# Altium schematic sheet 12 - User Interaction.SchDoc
size B; CompanyName: Microchip Technology Inc.; Organization: Microchip Technology; Address1: 2355 West Chandler Blvd.; Address2: Chandler, AZ  85224; Address4: USA; DocumentNumber: 12; SheetNumber: 12; SheetTotal: 13; SheetTitle: User Interaction
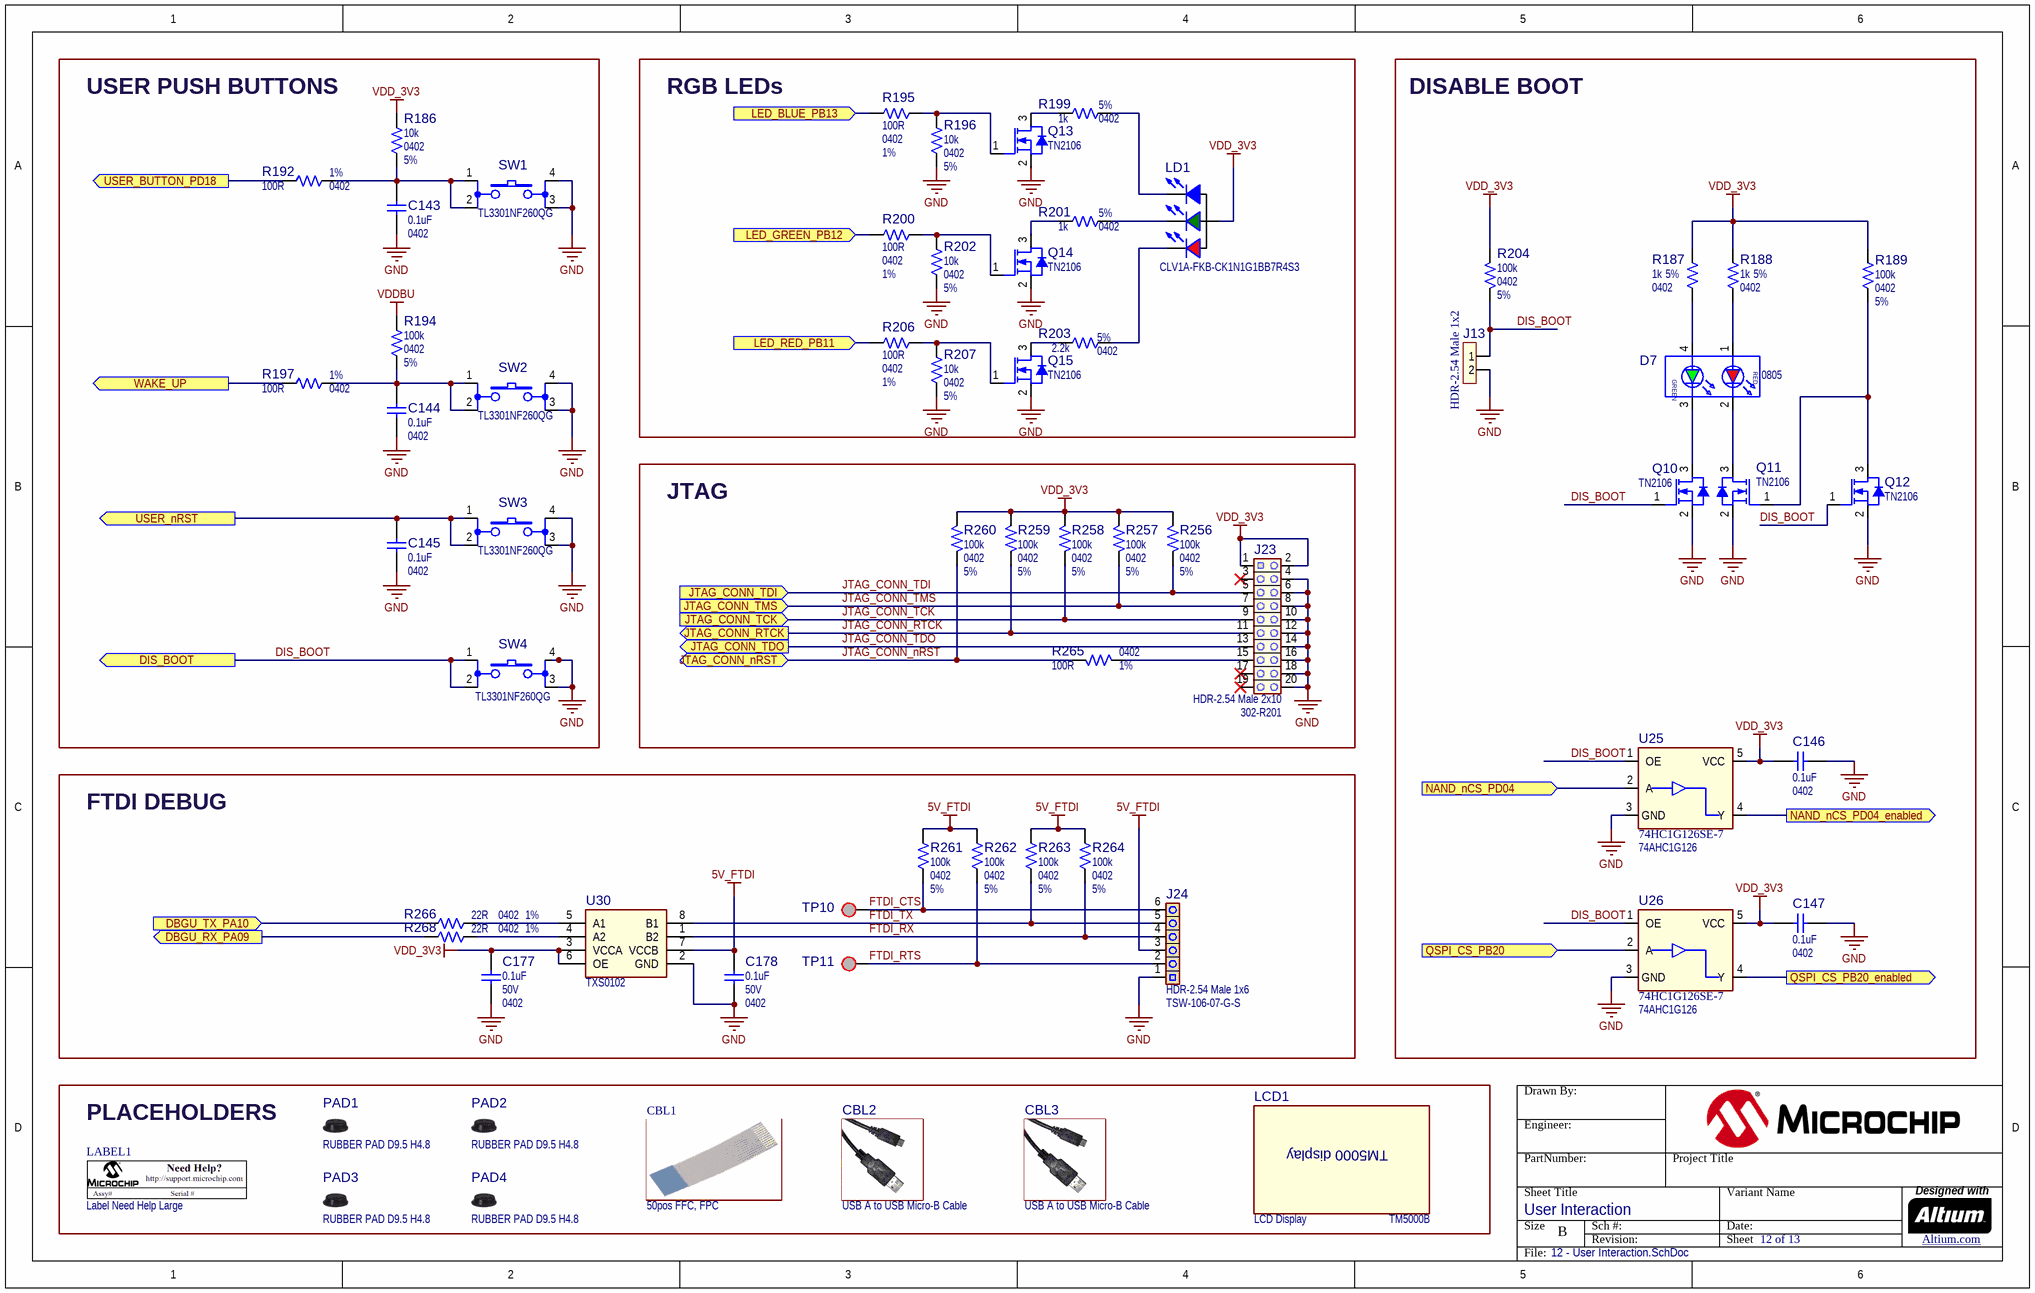
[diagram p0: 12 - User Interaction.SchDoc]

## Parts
?  (no value)  (graphical)
C143  value 0.1uF  Package: 0402  [CAP_C_0402]  (hidden comment: Capacitor NP)
C144  value 0.1uF  Package: 0402  [CAP_C_0402]  (hidden comment: Capacitor NP)
C145  value 0.1uF  Package: 0402  [CAP_C_0402]  (hidden comment: Capacitor NP)
C146  value 0.1uF  Package: 0402  [CAP_C_0402]  (hidden comment: Capacitor NP)
C147  value 0.1uF  Package: 0402  [CAP_C_0402]  (hidden comment: Capacitor NP)
C177  value 0.1uF  Voltage: 50V  Package: 0402  [CAP_C_0402]  (hidden comment: Capacitor NP)
C178  value 0.1uF  Voltage: 50V  Package: 0402  [CAP_C_0402]  (hidden comment: Capacitor NP)
CBL1  value 50pos FFC, FPC  (hidden comment: Cable FFC FPC Opposite Sided Contacts)  (mechanical)
CBL2  USB A to USB Micro-B Cable  (mechanical)
CBL3  USB A to USB Micro-B Cable  (mechanical)
D7  Package: 0805  [LED_DUAL_SMD_2x1.25mm]  (hidden comment: LED DUAL 4 pin)
J13  value HDR-2.54 Male 1x2  [HDR_M_2.54_1x2]  (hidden comment: Header 1x2)
J23  Voltage: HDR-2.54 Male 2x10  Manufacturer Part Number 1: 302-R201  [HDR_M_2.54_2X10_S_TH_RA_OS_302-R201]  (hidden comment: Header 2x10)
J24  value HDR-2.54 Male 1x6  Manufacturer Part Number 3: TSW-106-07-G-S  [HDR_M_2.54_1x6]  (hidden comment: Header 1x6)
LABEL1  value Label Need Help Large  [LABEL_Need_Help_Large]  (hidden comment: LABEL_Need_Help_Large)  (no BOM)
LCD1  value LCD Display  Manufacturer Part Number 1: TM5000B  [TM5000_mockup_model]  (hidden comment: TM5000 mechanical mockup)  (no BOM)
LD1  Manufacturer Part Number 1: CLV1A-FKB-CK1N1G1BB7R4S3  [PLCC-4_CLV1A-FKB]  (hidden comment: LED_RGB_CLV1A)
PAD1  value RUBBER PAD D9.5 H4.8  [BUMP_ ESSENTRA_RBS-35_CYLINDRICAL_CLEAR_D9.50H4.8]  (hidden comment: Rubber Pad Cylindrical)
PAD2  value RUBBER PAD D9.5 H4.8  [BUMP_ ESSENTRA_RBS-35_CYLINDRICAL_CLEAR_D9.50H4.8]  (hidden comment: Rubber Pad Cylindrical)
PAD3  value RUBBER PAD D9.5 H4.8  [BUMP_ ESSENTRA_RBS-35_CYLINDRICAL_CLEAR_D9.50H4.8]  (hidden comment: Rubber Pad Cylindrical)
PAD4  value RUBBER PAD D9.5 H4.8  [BUMP_ ESSENTRA_RBS-35_CYLINDRICAL_CLEAR_D9.50H4.8]  (hidden comment: Rubber Pad Cylindrical)
Q10  value TN2106  [SOT-23-3]  (hidden comment: Transistor MOS-N GSD)
Q11  value TN2106  [SOT-23-3]  (hidden comment: Transistor MOS-N GSD)
Q12  value TN2106  [SOT-23-3]  (hidden comment: Transistor MOS-N GSD)
Q13  value TN2106  [SOT-23-3]  (hidden comment: Transistor MOS-N GSD)
Q14  value TN2106  [SOT-23-3]  (hidden comment: Transistor MOS-N GSD)
Q15  value TN2106  [SOT-23-3]  (hidden comment: Transistor MOS-N GSD)
R186  value 10k  Package: 0402  Tolerance: 5%  [RES_C_0402]  (hidden comment: Resistor)
R187  value 1k  Package: 0402  Tolerance: 5%  [RES_C_0402]  (hidden comment: Resistor)
R188  value 1k  Package: 0402  Tolerance: 5%  [RES_C_0402]  (hidden comment: Resistor)
R189  value 100k  Package: 0402  Tolerance: 5%  [RES_C_0402]  (hidden comment: Resistor)
R192  value 100R  Package: 0402  Tolerance: 1%  [RES_C_0402]  (hidden comment: Resistor)
R194  value 100k  Package: 0402  Tolerance: 5%  [RES_C_0402]  (hidden comment: Resistor)
R195  value 100R  Package: 0402  Tolerance: 1%  [RES_C_0402]  (hidden comment: Resistor)
R196  value 10k  Package: 0402  Tolerance: 5%  [RES_C_0402]  (hidden comment: Resistor)
R197  value 100R  Package: 0402  Tolerance: 1%  [RES_C_0402]  (hidden comment: Resistor)
R199  value 1k  Package: 0402  Tolerance: 5%  [RES_C_0402]  (hidden comment: Resistor)
R200  value 100R  Package: 0402  Tolerance: 1%  [RES_C_0402]  (hidden comment: Resistor)
R201  value 1k  Package: 0402  Tolerance: 5%  [RES_C_0402]  (hidden comment: Resistor)
R202  value 10k  Package: 0402  Tolerance: 5%  [RES_C_0402]  (hidden comment: Resistor)
R203  value 2.2k  Package: 0402  Tolerance: 5%  [RES_C_0402]  (hidden comment: Resistor)
R204  value 100k  Package: 0402  Tolerance: 5%  [RES_C_0402]  (hidden comment: Resistor)
R206  value 100R  Package: 0402  Tolerance: 1%  [RES_C_0402]  (hidden comment: Resistor)
R207  value 10k  Package: 0402  Tolerance: 5%  [RES_C_0402]  (hidden comment: Resistor)
R256  value 100k  Package: 0402  Tolerance: 5%  [RES_C_0402]  (hidden comment: Resistor)
R257  value 100k  Package: 0402  Tolerance: 5%  [RES_C_0402]  (hidden comment: Resistor)
R258  value 100k  Package: 0402  Tolerance: 5%  [RES_C_0402]  (hidden comment: Resistor)
R259  value 100k  Package: 0402  Tolerance: 5%  [RES_C_0402]  (hidden comment: Resistor)
R260  value 100k  Package: 0402  Tolerance: 5%  [RES_C_0402]  (hidden comment: Resistor)
R261  value 100k  Package: 0402  Tolerance: 5%  [RES_C_0402]  (hidden comment: Resistor)
R262  value 100k  Package: 0402  Tolerance: 5%  [RES_C_0402]  (hidden comment: Resistor)
R263  value 100k  Package: 0402  Tolerance: 5%  [RES_C_0402]  (hidden comment: Resistor)
R264  value 100k  Package: 0402  Tolerance: 5%  [RES_C_0402]  (hidden comment: Resistor)
R265  value 100R  Package: 0402  Tolerance: 1%  [RES_C_0402]  (hidden comment: Resistor)
R266  value 22R  Package: 0402  Tolerance: 1%  [RES_C_0402]  (hidden comment: Resistor)
R268  value 22R  Package: 0402  Tolerance: 1%  [RES_C_0402]  (hidden comment: Resistor)
SW1  Manufacturer Part Number 2: TL3301NF260QG  [SW_SMD_6mmX6mm_TL3301]  (hidden comment: Switch 4 Pin)
SW2  Manufacturer Part Number 2: TL3301NF260QG  [SW_SMD_6mmX6mm_TL3301]  (hidden comment: Switch 4 Pin)
SW3  Manufacturer Part Number 2: TL3301NF260QG  [SW_SMD_6mmX6mm_TL3301]  (hidden comment: Switch 4 Pin)
SW4  Manufacturer Part Number 2: TL3301NF260QG  [SW_SMD_6mmX6mm_TL3301]  (hidden comment: Switch 4 Pin)
TP10  SMD Test Point  [TP_1x1_SMD]  (value not drawn)  (no BOM)
TP11  SMD Test Point  [TP_1x1_SMD]  (value not drawn)  (no BOM)
U25  74HC1G126SE-7  value 74AHC1G126  [SC-70-5]
U26  74HC1G126SE-7  value 74AHC1G126  [SC-70-5]
U30  TXS0102  [US-8]

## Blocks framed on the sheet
USER PUSH BUTTONS: C143-C145 R186 R192 R194 R197 SW1-SW4
RGB LEDs: LD1 Q13-Q15 R195 R196 R199-R203 R206 R207
DISABLE BOOT: C146 C147 D7 J13 Q10-Q12 R187-R189 R204 U25 U26
JTAG: J23 R256-R260 R265
FTDI DEBUG: C177 C178 J24 R261-R264 R266 R268 TP10 TP11 U30
PLACEHOLDERS: CBL1-CBL3 LABEL1 LCD1 PAD1-PAD4

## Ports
DBGU_RX_PA09 (out), DBGU_TX_PA10 (in), DIS_BOOT (out), JTAG_CONN_nRST (bidir), JTAG_CONN_RTCK (out), JTAG_CONN_TCK (in), JTAG_CONN_TDI (in), JTAG_CONN_TDO (out), JTAG_CONN_TMS (in), LED_BLUE_PB13 (in), LED_GREEN_PB12 (in), LED_RED_PB11 (in), NAND_nCS_PD04 (in), NAND_nCS_PD04_enabled (out), QSPI_CS_PB20 (in), QSPI_CS_PB20_enabled (out), USER_BUTTON_PD18 (out), USER_nRST (out), WAKE_UP (out)

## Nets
5V_FTDI: C178.2 J24.3 R261.1 R262.1 R263.2 R264.2 U30.7(VCCB)
GND: C143.2 C144.2 C145.2 C146.1 C147.1 C177.1 C178.1 J13.2 J23.4 J23.6 J23.8 J23.10 J23.12 J23.14 J23.16 J23.18 J23.20 J24.1 Q10.2(S) Q11.2(S) Q12.2(S) Q13.2(S) Q14.2(S) Q15.2(S) R196.2 R202.2 R207.2 SW1.3 SW1.4 SW2.3 SW2.4 SW3.3 SW3.4 SW4.3 SW4.4 U25.3(GND) U26.3(GND) U30.2(GND)
VDD_3V3: C146.2 C147.2 C177.2 J23.1 J23.2 LD1.2(A) R186.1 R187.1 R188.1 R189.2 R204.2 R256.2 R257.2 R258.1 R259.1 R260.2 U25.5(VCC) U26.5(VCC) U30.3(VCCA) U30.6(OE)
VDDBU: R194.2
DBGU_RX_PA09: R268.1 ; port DBGU_RX_PA09
DBGU_TX_PA10: R266.1 ; port DBGU_TX_PA10
DIS_BOOT: J13.1 Q10.1(G) Q12.1(G) R204.1 SW4.1 SW4.2 U25.1(OE) U26.1(OE) ; port DIS_BOOT
FTDI_CTS: J24.6 R261.2 TP10.1
FTDI_RTS: J24.2 R262.2 TP11.1
FTDI_RX: J24.4 R264.1 U30.1(B2)
FTDI_TX: J24.5 R263.1 U30.8(B1)
JTAG_CONN_nRST: R260.1 R265.1 ; port JTAG_CONN_nRST
JTAG_CONN_RTCK: J23.11 R259.2 ; port JTAG_CONN_RTCK
JTAG_CONN_TCK: J23.9 R258.2 ; port JTAG_CONN_TCK
JTAG_CONN_TDI: J23.5 R256.1 ; port JTAG_CONN_TDI
JTAG_CONN_TDO: J23.13 ; port JTAG_CONN_TDO
JTAG_CONN_TMS: J23.7 R257.1 ; port JTAG_CONN_TMS
LED_BLUE_PB13: R195.1 ; port LED_BLUE_PB13
LED_GREEN_PB12: R200.1 ; port LED_GREEN_PB12
LED_RED_PB11: R206.1 ; port LED_RED_PB11
NAND_nCS_PD04: U25.2(A) ; port NAND_nCS_PD04
NAND_nCS_PD04_enabled: U25.4(Y) ; port NAND_nCS_PD04_enabled
QSPI_CS_PB20: U26.2(A) ; port QSPI_CS_PB20
QSPI_CS_PB20_enabled: U26.4(Y) ; port QSPI_CS_PB20_enabled
USER_BUTTON_PD18: R192.1 ; port USER_BUTTON_PD18
USER_nRST: C145.1 SW3.1 SW3.2 ; port USER_nRST
WAKE_UP: R197.1 ; port WAKE_UP
NetC143_1: C143.1 R186.2 R192.2 SW1.1 SW1.2
NetC144_1: C144.1 R194.1 R197.2 SW2.1 SW2.2
NetD7_1: D7.1(A1) R188.2
NetD7_2: D7.2(K1) Q11.3(D)
NetD7_3: D7.3(K2) Q10.3(D)
NetD7_4: D7.4(A2) R187.2
NetJ23_15: J23.15 R265.2
NetLD1_1: LD1.1(Kr) R203.2
NetLD1_3: LD1.3(Kb) R199.2
NetLD1_4: LD1.4(Kg) R201.2
NetQ11_1: Q11.1(G) Q12.3(D) R189.1
NetQ13_1: Q13.1(G) R195.2 R196.1
NetQ13_3: Q13.3(D) R199.1
NetQ14_1: Q14.1(G) R200.2 R202.1
NetQ14_3: Q14.3(D) R201.1
NetQ15_1: Q15.1(G) R206.2 R207.1
NetQ15_3: Q15.3(D) R203.1
NetR266_2: R266.2 U30.5(A1)
NetR268_2: R268.2 U30.4(A2)

Not connected (* = marked no-connect by the designer): J23 3* 17* 19*

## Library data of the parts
? = Title Block B
C143-C147 = CAP1463: Capacitor; Manufacturer 1: TDK Corporation; Manufacturer Part Number 1: C1005X7R1H104K050BB; Voltage: 50V; Description_: CAP CER 0.1uF 50V 10% X7R SMD 0402; Dev Tools Status: Production; Tolerance: 10%; Temperature Coeffcient: X7R; Type: Ceramic; Owner: Jamus Griego; Populated: YES
C177 C178 = CAP1463: Capacitor; Manufacturer 1: TDK Corporation; Manufacturer Part Number 1: C1005X7R1H104K050BB; Description_: CAP CER 0.1uF 50V 10% X7R SMD 0402; Dev Tools Status: Production; Tolerance: 10%; Temperature Coeffcient: X7R; Type: Ceramic; Owner: Jamus Griego; Populated: YES
CBL1 = CAB1019: Manufacturer 1: Wurth Electronics Inc.; Manufacturer Part Number 1: 687750100002; Description_: MECH HW CABLE FFC, FPC 50pos 0.50mm 100mm; Dev Tools Status: Design; Owner: Ilie Galan; Populated: MECH
CBL2 CBL3 = CAB1020: Manufacturer 1: Assmann WSW Components; Manufacturer Part Number 1: AK67421-1; Description_: MECH HW CABLE USB Male A TO USB Male Micro-B 1M; Dev Tools Status: Design; Owner: Ilie Galan; Populated: MECH
D7 = DIODE1110: LED; Manufacturer 1: Kingbright Corp; Manufacturer Part Number 1: APHBM2012SURKCGKC; Value: RED, GREEN; Description_: DIO LED BI RED, GREEN 1.95V, 2.1V 30mA 0805; Dev Tools Status: Production; Type: LED Bicolor; Forward Current: 30mA; Power: 75mW; Reverse Current: 10uA; Owner: Bogdan P (M91398); Populated: Yes
J13 = CON1312: Manufacturer 1: Sullins Connector Solutions; Manufacturer Part Number 1: PREC002SAAN-RC; Description_: CON HDR-2.54 Male 1x2 Tin 5.84MH TH VERT; Dev Tools Status: Production; Owner: Randolph Sobrepena; Populated: YES
J23 = CON1883: Manufacturer 1: On Shore Technology Inc.; Description_: CONN HDR-2.54 MALE 2x10 GOLD SHROUD 3.10MH TH R/A; Dev Tools Status: Design; Owner: Ilie Galan; Current: 3A; Populated: YES
J24 = CON1106: Manufacturer 1: FCI; Manufacturer Part Number 1: 68000-106HLF; Description_: CON HDR-2.54 Male 1x6 Gold 5.84MH TH VERT; Dev Tools Status: Production; Owner: Bogdan P (M91398); Populated: Yes
LABEL1 = 08-00126: Description_: LABEL, NEED HELP WITH ASSY/SERIAL; Dev Tools Status: Production; Populated: MECH
LCD1 = DISPLAY0025: Manufacturer 1: PDA INC; Description_: DISPLAY LCD TM5000B 5" GRAPHICAL 5V SCREWS; Dev Tools Status: Design; Owner: Dragos Danaila; Voltage: 5V; Populated: YES
LD1 = DIODE1214: Manufacturer 1: Cree Inc; Value: RED, GREEN, BLUE; Description_: DIO LED TRI RED, GREEN, BLUE 2V, 3.2V, 3.2V 20mA, 20mA, 20mA SMD 4-PLCC; Dev Tools Status: Production; Type: LED Tricolor; Forward Current: 20mA, 20mA, 20mA; Power: 130mW, 100mW, 100mW; Reverse Current: 10uA; Reverse Voltage: 5V; Owner: Randolph Sobrepena; Populated: YES
PAD1-PAD4 = MECH0185: Manufacturer 1: Essentra Components; Manufacturer Part Number 1: RBS-35; Description_: MECH HW RUBBER PAD Cylindrical, 0.374" x 0.189" Clear; Dev Tools Status: Design; Owner: Sam Charles; Populated: MECH
Q10-Q15 = MIC7420: Transistor MOS; Manufacturer 1: Microchip Technology; Manufacturer Part Number 1: TN2106K1-G; Description_: MCHP ANALOG MOSFET N-CH TN2106 60V 280mA 360mW 2.5R SOT23-3; Type: MOSFET; Dev Tools Status: Production; Owner: Ilie Galan; Populated: YES
R186 R196 R202 = RSMT0439: Manufacturer 1: Vishay; Manufacturer Part Number 1: CRCW040210K0JNED; Description_: RES TKF 10k 5% 1/16W SMD 0402; Dev Tools Status: Production; Voltage: 50V; Temperature Coeffcient: 100ppm/C; Power: 1/16W; Populated: Yes
R187 R188 R199 R201 = RSMT0316: Manufacturer 1: Panasonic; Manufacturer Part Number 1: ERJ-2GEJ102X; Description_: RES TKF 1k 5% 1/16W SMD 0402; Dev Tools Status: Production; Voltage: 50V; Temperature Coeffcient: 200ppm/C; Power: 1/16W; Owner: Tad Ahlvers; Populated: YES
R189 R194 R204 R256 R257 R260 R263 R264 = RES2196: Manufacturer 1: Yageo; Manufacturer Part Number 1: RC0402JR-07100KL; Description_: RES TKF 100k 5% 1/16W SMD 0402; Dev Tools Status: Design; Temperature Coeffcient: 100ppm/C; Power: 1/16W; Owner: Ilie Galan; Populated: YES
R192 R195 R197 R200 R206 R265 = RES1587: Manufacturer 1: Yageo; Manufacturer Part Number 1: RC0402FR-07100RL; Description_: RES TKF 100R 1% 1/16W SMD 0402; Dev Tools Status: Design; Voltage: 50V; Temperature Coeffcient: 100ppm/C; Power: 1/16W; Owner: Sorin Stanoaia; Populated: YES
R203 = RES1020: Manufacturer 1: Vishay Dale; Manufacturer Part Number 1: CRCW04022K20JNED; Description_: RES TKF 2.2k 5% 1/16W SMD 0402; Dev Tools Status: Production; Voltage: 50V; Temperature Coeffcient: 200ppm/C; Power: 1/16W; Owner: Tad Ahlvers; Populated: YES
R207 = RSMT0439: Manufacturer 1: Vishay; Manufacturer Part Number 1: CRCW040210K0JNED; Description_: RES TKF 10k 5% 1/16W SMD 0402; Dev Tools Status: Production; Voltage: 50V; Temperature Coeffcient: 100ppm/C; Power: 1/16W; Populated: DNP
R258 R259 R261 R262 = RES2196: Manufacturer 1: Yageo; Manufacturer Part Number 1: RC0402JR-07100KL; Description_: RES TKF 100k 5% 1/16W SMD 0402; Dev Tools Status: Design; Temperature Coeffcient: 100ppm/C; Power: 1/16W; Owner: Ilie Galan; Populated: DNP
R266 R268 = RES1474: Manufacturer 1: Panasonic Electronic Components; Manufacturer Part Number 1: ERJ-2RKF22R0X; Description_: RES TKF 22R 1% 1/20W SMD 0402; Dev Tools Status: Production; Temperature Coeffcient: 100ppm/C; Circuit Type: Isolated; Power: 1/10W; Owner: Mike Ragsdale; Populated: YES
SW1-SW4 = SWITCH0003: Switch; Manufacturer 1: E-Switch; Manufacturer Part Number 1: TL3301NF260QG/TR; Value: TACT SPST; Description_: SWITCH TACT SPST 12V 50mA TL3301NF160QG/TR SMD; Dev Tools Status: Production; Voltage: 12V; Current: 50mA; Populated: Yes
TP10 TP11 = TEST-POINT: Test Point pad 1.00mm
U25 U26 = IC1252: Single  Non-Inverting 3-State  buffer; Manufacturer 1: Diodes Incorporated; Manufacturer Part Number 1: 74AHC1G126SE-7; MCHP-ID: IC1252; Description_: IC BUFFER 74AHC1G126SE-7 SINGLE SC-70-5; Dev Tools Status: Design; Owner: Ed Kennedy; Populated: YES
U30 = IC1128: Level Shifter; Manufacturer 1: Texas Instruments; Manufacturer Part Number 1: TXS0102DCUR; MCHP-ID: IC1128; Description_: IC TRANSCEIVER TXS0102 US-8; Dev Tools Status: Production; Owner: Bogdan P (M91398); Populated: Yes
